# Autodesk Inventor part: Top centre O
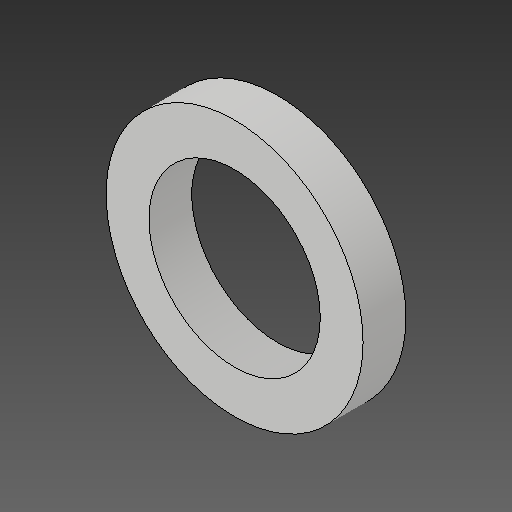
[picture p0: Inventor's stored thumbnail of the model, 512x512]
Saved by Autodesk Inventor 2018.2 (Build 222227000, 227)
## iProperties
Created: 2018-03
Part Number: Top centre O
Material: Generic
Document SubType Name: Modeling
Designer: PeterMaxwell-Stewart
Mass: 1.9635 g
Surface Area: 15.708 cm^2
Volume: 1.9635 cm^3
Density: 1 g/cm^3
Appearance: Default
Author: PeterMaxwell-Stewart
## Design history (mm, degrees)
derived "O's and X's.ipt"
feature "Top centre O::O's and X's.ipt" dims "d0" = 10
tag "TaggingFeature1"
body "Solid1"
